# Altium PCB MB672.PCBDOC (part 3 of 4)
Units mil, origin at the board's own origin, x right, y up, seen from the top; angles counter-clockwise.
Board outline 4505 x 6805 mil, 4 copper layers (TopLayer, GND, VCC, BottomLayer); 337 components, 289 nets, 1516 pads, 621 vias.
Unrouted connection lines stored in the file: 46.
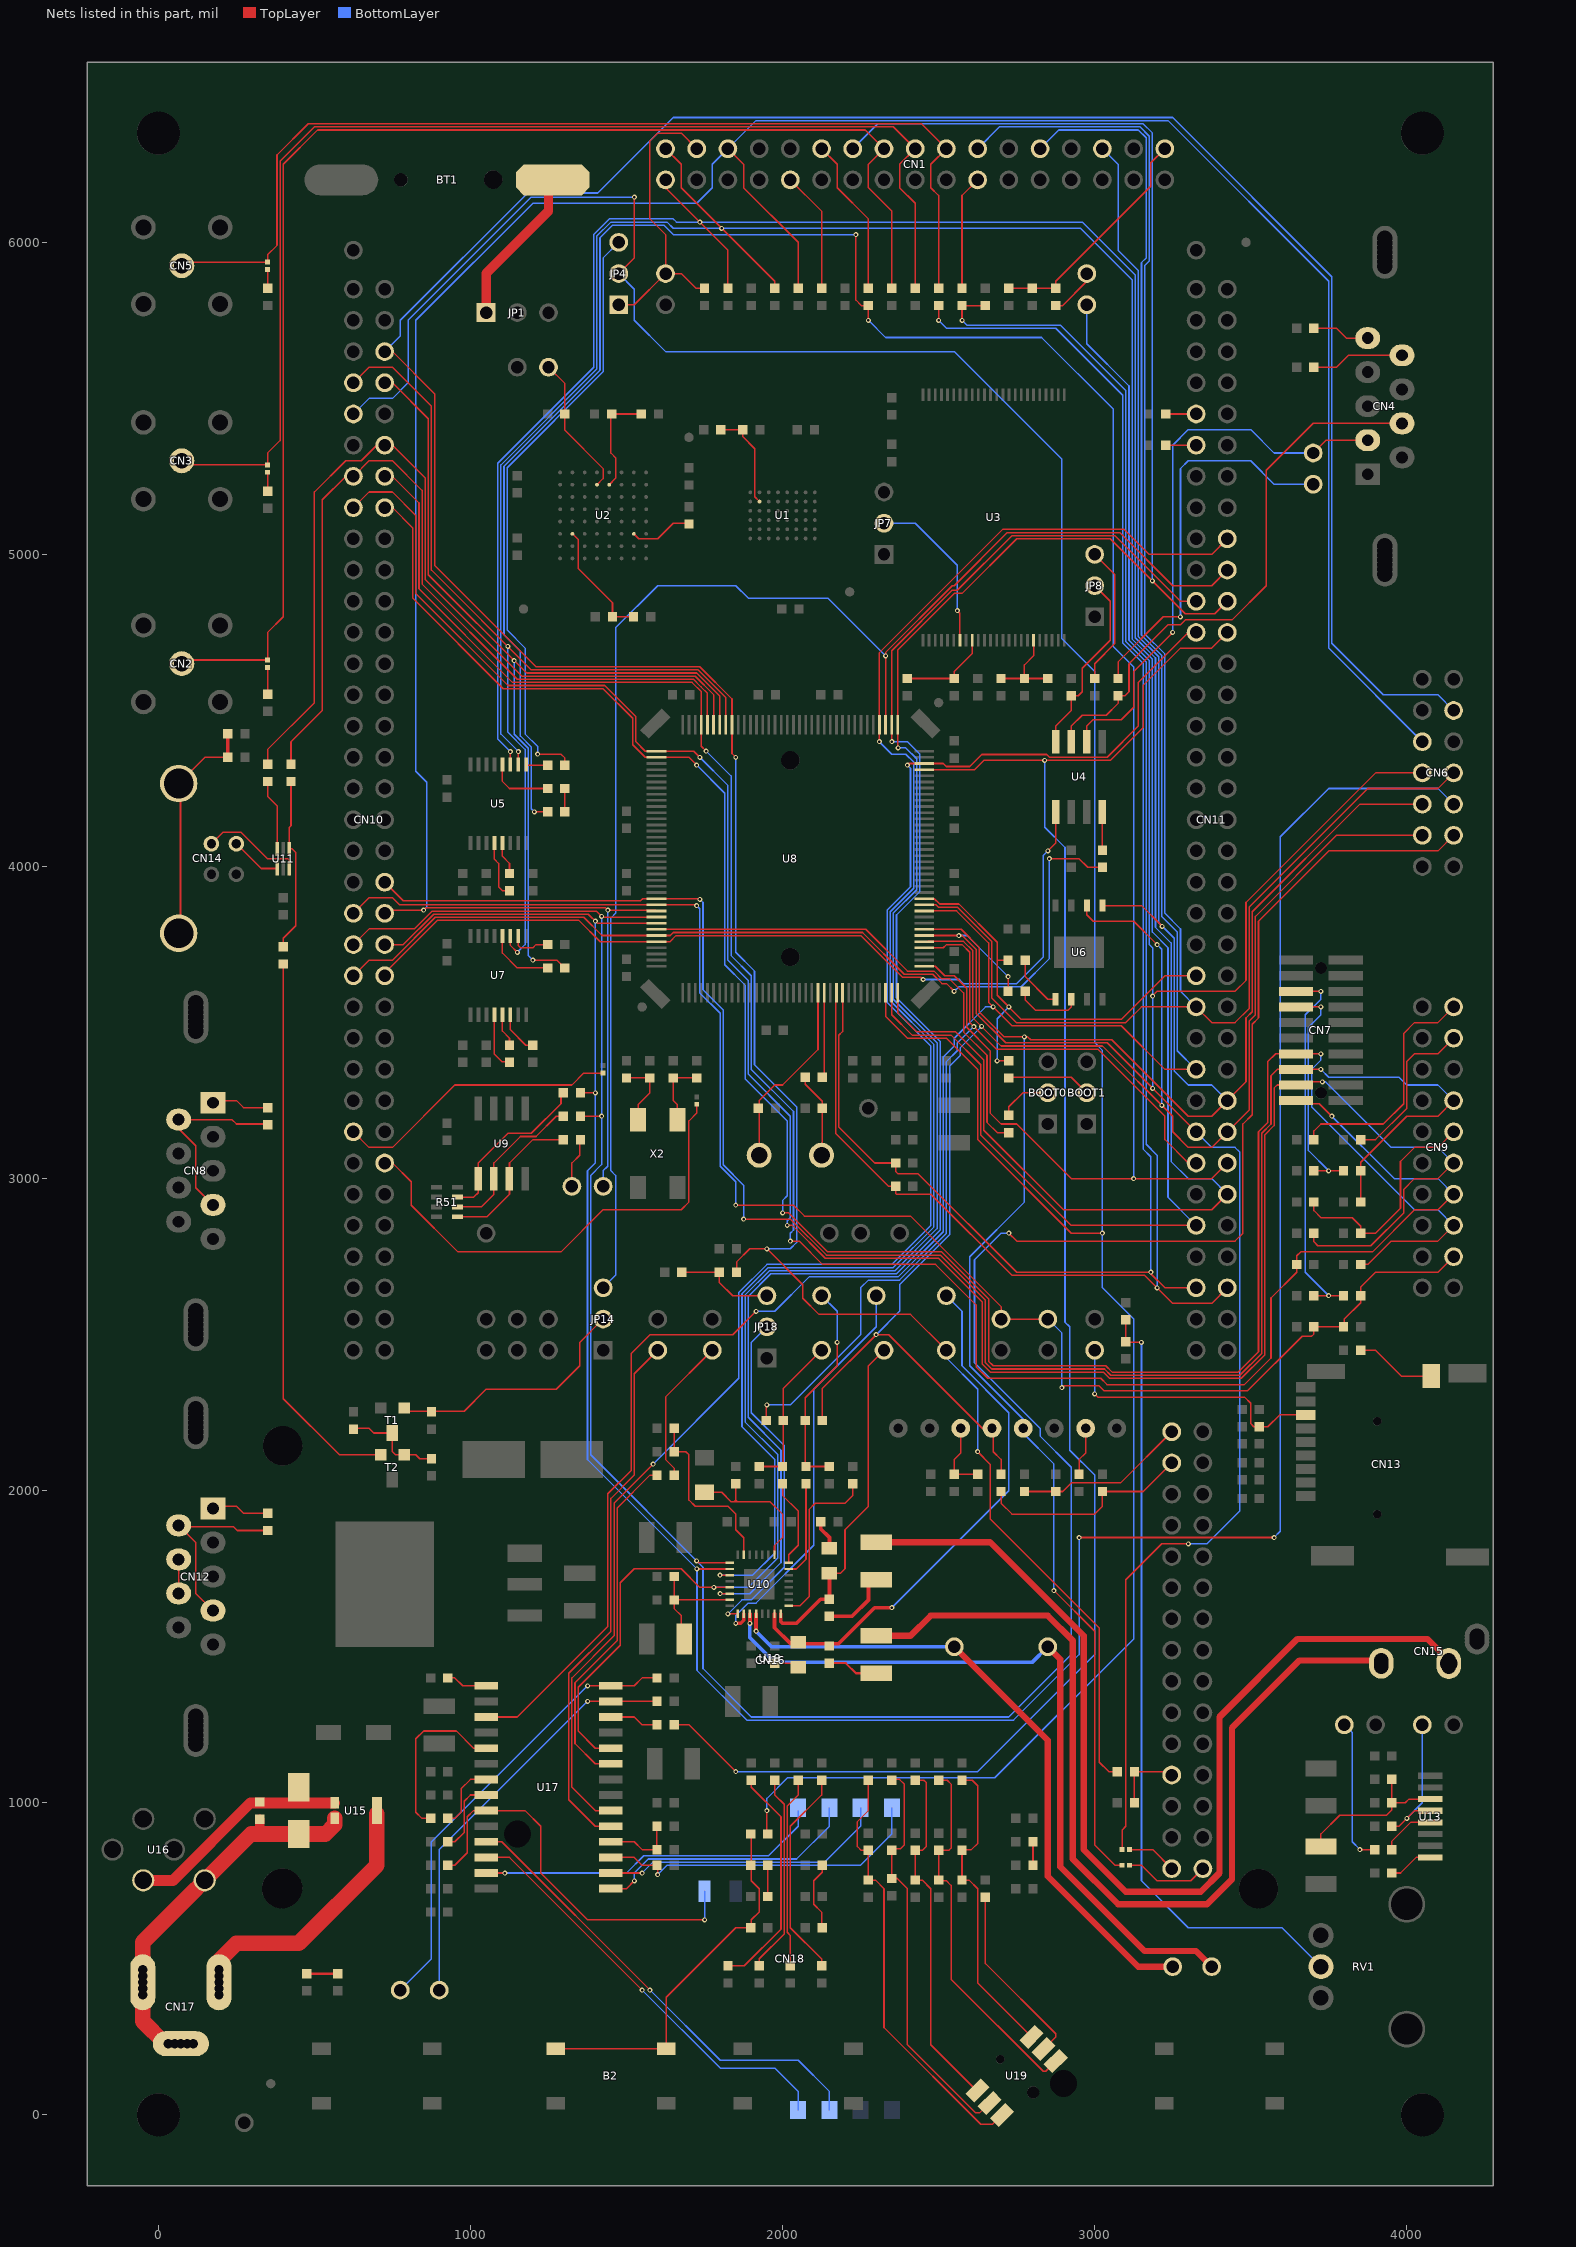
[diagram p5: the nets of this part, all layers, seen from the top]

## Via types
v1: diameter 16, hole 8, TopLayer to BottomLayer, tented both sides, 621 vias

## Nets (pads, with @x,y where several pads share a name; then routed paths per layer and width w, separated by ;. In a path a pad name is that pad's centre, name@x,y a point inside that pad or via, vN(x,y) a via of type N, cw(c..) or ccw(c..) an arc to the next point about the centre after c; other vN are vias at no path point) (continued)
NetC42_2: C42.2 U7.6 | length 140.5
  TopLayer w5: U7.6@1127.95,3525 1127.95,3477.05 1177.5,3427.5 C42.2@1200,3427.5
NetC43_1: C43.1 R135.1 X2.1 | length 225
  TopLayer w5: R135.1@1500,3322.5 C43.1@1575,3322.5 1575,3275 1537.01,3237.01 X2.1@1537.01,3188.27
NetC47_1: C47.1 U8.23 X1.2 | length 616.1
  TopLayer w5: X1.2@1902.5,3077.5 X1.2@1902.5,3080 ; X1.2@1925,3075 1925,3250 1975,3300 2000,3300 2113.58,3413.58 U8.23@2113.58,3595.87
NetC48_1: C48.1 R40.2 X1.1 | length 270.3
  TopLayer w5: R40.2@2072.5,3325 2072.5,3302.5 2127.5,3247.5 X1.1@2127.5,3077.5
NetC56_2: C55.2 C56.2 R67.1 TP9.1 | length 498.2
  TopLayer w5: C55.2@1925,2077.5 C56.2@2000,2077.5 C56.2@2000,2080 ; C56.2@2002.5,2080 2002.5,2327.5 TP9.1@2125,2450
NetC57_2: C57.2 C58.2 R68.1 TP6.1 | length 758.2
  TopLayer w5: C57.2@2072.5,2080 2072.5,2297.5 2175,2400 v1(2175,2475) ; C57.2@2075,2077.5 C58.2@2150,2077.5 C57.2@2075,2077.5
  BottomLayer w5: TP6.1@2125,2625 2175,2575 v1(2175,2475)
NetC59_1: C59.1 U10.25 | length 553.6
  TopLayer w5: U10.25@2019.49,1631.1 2056.1,1631.1 2085,1660 2085,1940 2105,1960 2200,1960 2225,1985 C59.1@2225,2022.5
NetC67_2: C67.2 R73.1 | length 96.4
  TopLayer w12: R73.1@2122.5,1900 2122.5,1877.5 2150,1850 C67.2@2150,1815
NetC70_2: C70.2 CN15.2 | length 3356.5
  TopLayer w20: C70.2@2300,1835 2665,1835 2965,1535 2965,850 3100,715 3340,715 3400,775 3400,1275 3650,1525 4065.71,1525 CN15.2@4134.45,1456.26
NetC76_2: C76.2 R86.1 | length 82.5
  TopLayer w5: R86.1@1975,1447.5 C76.2@2057.5,1447.5
NetC78_2: C78.2 CN14.0 R95.2 | length 759.9
  TopLayer w5: CN14.0@65,4266 149,4350 R95.2@222.5,4350 ; CN14.0@70.79,3779.21 CN14.0@70.79,4271.79
  TopLayer w12: R95.2@222.5,4350 C78.2@222.5,4425
NetC80_2: C80.2 CN15.3 | length 3045.7
  TopLayer w20: C80.2@2300,1535 2410,1535 2475,1600 2850,1600 2930,1520 2930,820 3075,675 3360,675 3440,755 3440,1240 3656.26,1456.26 CN15.3@3917.91,1456.26
NetC87_1: C87.1 U17.7 | length 218.2
  TopLayer w5: C87.1@927.5,950 950,950 970,970 970,1045 1000,1075 U17.7@1050,1075
NetC90_2: C90.2 CN18.1 U17.17 | length 1073.5
  TopLayer w5: U17.17@1450,825 1525,825 1550,800 C90.2@1597.5,800 ; v1(1600,770) C90.2@1600,797.5
  BottomLayer w5: v1(1600,770) 1630,800 2250,800 2350,900 CN18.1@2350,984.25
NetC91_1: C91.1 R120.2 | length 100
  TopLayer w5: R120.2@1952.5,700 C91.1@1952.5,800
NetC91_2: B2.2 B2.3 C91.2 R110.1 R123.1 | length 1197.3
  TopLayer w5: B2.2@1272.83,212.5 B2.3@1627.17,212.5 1627.17,377.17 1850,600 R123.1@1897.5,600 ; R123.1@1900,602.5 1900,625 1925,650 1925,725 1900,750 R110.1@1900,897.5
NetC92_1: C92.1 R124.2 | length 219.2
  TopLayer w5: R124.2@2125,602.5 2125,650 2100,675 2100,750 2127.5,777.5 C92.1@2127.5,800
NetC93_1: C93.1 R117.2 | length 75
  TopLayer w5: C93.1@2802.5,800 R117.2@2802.5,875
NetCN1_14: CN1.14 R6.1 | length 368.2
  TopLayer w5: R6.1@2575,5852.5 2575,6150 CN1.14@2625,6200
NetCN1_26: CN1.26 R1.1 | length 388.9
  TopLayer w5: CN1.26@2025,6200 2125,6100 R1.1@2125,5852.5
NetCN7_14: CN7.14 R49.1 R50.1 | length 743.5
  TopLayer w5: CN7.14@3645,3550 v1(3725,3550) ; R49.1@3702.5,3025 R50.1@3797.5,3025
  BottomLayer w5: v1(3725,3550) 3725,3525 3685,3485 3685,3090 v1(3750,3025)
NetCN7_16: CN7.16 R60.1 R61.1 | length 1201.8
  TopLayer w5: CN7.16@3645,3600 v1(3725,3600) ; R60.1@3702.5,2625 R61.1@3797.5,2625
  BottomLayer w5: v1(3725,3600) 3725,3575 3675,3525 3675,2700 v1(3750,2625)
NetCN9_11: CN9.11 R52.2 R55.1 | length 740.7
  TopLayer w5: R52.2@3702.5,2925 3702.5,2897.5 3725,2875 3825,2875 3852.5,2847.5 R55.1@3852.5,2825 3900,2825 3980,2905 3980,3055 4025,3100 4100,3100 CN9.11@4150,3150
NetCN9_17: CN9.17 R48.1 | length 520
  TopLayer w5: R48.1@3852.5,3125 3900,3125 4000,3225 4000,3375 4025,3400 4100,3400 CN9.17@4150,3450
NetCN9_19: CN9.19 R47.1 | length 771.5
  TopLayer w5: R47.1@3702.5,3125 3702.5,3152.5 3725,3175 3925,3175 3990,3240 3990,3465 4025,3500 4100,3500 CN9.19@4150,3550
NetCN10_58: CN10.58 JP10.1 | length 1526.8
  TopLayer w5: CN10.58@725,3050 750,3050 810,2990 810,2915 960,2765 1290,2765 1425,2900 1675,2900 1700,2925 1700,3185 1725,3210 JP10.1@1725,3238.19
NetCN12_7: CN12.7 CN12.8 | length 105
  TopLayer w5: CN12.8@65,1675 CN12.7@65,1780
NetCN14_2: CN14.2 U11.1 | length 163.2
  TopLayer w5: CN14.2@250,4073 329.3,3993.7 U11.1@380.32,3993.7
NetCN14_3: CN14.3 U11.3 | length 347.2
  TopLayer w5: CN14.3@170,4073 207,4110 265,4110 350,4025 415,4025 419.68,4020.32 U11.3@419.68,3993.7
  TopLayer w7: U11.3@419.68,3975.32 U11.3@419.68,3993.7
NetCN17_1: CN17.1 U15.1 | length 886.7
  TopLayer w50: CN17.1@194.09,405 194.09,494.09 250,550 450,550 700,800 U15.1@700,965
NetCN17_3: C85.2 CN17.2 CN17.3 U15.2 U16.2 Z1.1 | length 1270.5
  TopLayer w30: 325,900.2 C85.2@325,947.5
  TopLayer w50: CN17.2@100,230 20,230 -50,300 -50,553.15 297.05,900.2 535.2,900.2 565,930 U15.2@565,950
NetCN18_2: CN18.2 U17.16 | length 921.4
  TopLayer w5: U17.16@1450,775 v1(1550,775)
  BottomLayer w5: v1(1550,775) 1585,810 2135,810 2250,925 CN18.2@2250,984.25
NetCN18_3: CN18.3 U17.15 | length 856.7
  TopLayer w5: U17.15@1450,725 1500,725 v1(1525,750)
  BottomLayer w5: v1(1525,750) 1525,775 1570,820 2045,820 2150,925 CN18.3@2150,984.25
NetJP1_1: BT1.1 JP1.1 | length 915.7
  TopLayer w5: JP1.1@1050,5775 1050,5900 1250,6100
  TopLayer w30: JP1.1@1050,5775 1050,5900 1250,6100 BT1.1@1250,6200
NetJP3_2: JP3.2 R8.2 | length 157.1
  TopLayer w5: R8.2@2875,5797.5 2897.5,5797.5 2975,5875 JP3.2@2975,5900
NetJP4_1: C1.2 CN1.31 JP2.1 JP4.1 | length 962.9
  TopLayer w5: JP4.1@1475,5800 1525,5800 JP2.1@1625,5900 ; CN1.31@1725,6300 1675,6350 1600,6350 1575,6325 1575,6075 1625,6025 JP2.1@1625,5900 ; C1.2@1750,5852.5 1722.5,5852.5 1675,5900 JP2.1@1625,5900
NetJP4_3: JP4.3 R30.2 | length 1943.6
  TopLayer w5: v1(1215,4360) 1290,4360 1302.5,4347.5 R30.2@1302.5,4325
  BottomLayer w5: v1(1215,4360) 1215,4385 1175,4425 1175,4700 1117.5,4757.5 1117.5,5277.5 1425,5585 1425,5950 JP4.3@1475,6000
NetJP7_2: JP7.2 U3.7 | length 534.3
  TopLayer w5: v1(2560,4820) 2568.11,4811.89 U3.7@2568.11,4725
  BottomLayer w5: JP7.2@2325,5100 2425,5100 2560,4965 v1(2560,4820)
NetJP8_3: JP8.3 R27.1 | length 451.3
  TopLayer w5: R27.1@3000,4602.5 3000,4650 3065,4715 3065,4935 JP8.3@3000,5000
NetJP9_2: CN10.55 JP9.2 | length 919.4
  TopLayer w5: CN10.55@625,3150 675,3100 750,3100 950,3300 1325,3300 1363.19,3338.19 JP9.2@1425,3338.19
NetJP11_2: JP11.2 R46.2 | length 157.9
  TopLayer w5: JP11.2@1325,2975 1325,3050 1350,3075 R46.2@1350,3122.5
NetJP15_2: JP15.2 U17.19 | length 1728.3
  TopLayer w5: U17.19@1450,925 1400,925 1315,1010 1315,1415 1450,1550 1450,1975 1525,2050 1525,2375 JP15.2@1600,2450
NetJP16_2: JP16.2 R71.1 | length 473.5
  TopLayer w5: R71.1@1652.5,2050 1652.5,2072.5 1625,2100 1625,2300 JP16.2@1775,2450
NetJP17_2: CN13.7 JP17.2 R130.2 | length 913.9
  TopLayer w5: v1(3000,2310) 3010,2300 3480,2300 3500,2280 3500,2215 3510,2205 3555,2205 3592.91,2242.91 CN13.7@3676.65,2242.91
  BottomLayer w5: v1(3000,2310) JP17.2@3000,2450
NetJP18_2: JP18.2 U10.17 | length 1107.6
  TopLayer w5: v1(1825,1605) 1825.51,1605.51 U10.17@1856.1,1605.51
  BottomLayer w5: v1(1825,1605) 1870,1650 1900,1650 2005,1755 2005,2145 1900,2250 1900,2475 JP18.2@1950,2525
NetJP21_1: JP21.1 R88.1 U13.5 | length 463.8
  TopLayer w5: R88.1@3952.5,925 3975,925 4024.61,974.61 U13.5@4075,974.61
  BottomLayer w5: v1(4000,950) 4050,1000 JP21.1@4050,1250
NetJP22_2: JP22.2 R89.2 | length 468.2
  TopLayer w5: v1(3850,850) R89.2@3897.5,850
  BottomLayer w5: JP22.2@3800,1250 3825,1225 3825,875 v1(3850,850)
NetJP25_2: JP25.2 R138.1 | length 60.7
  TopLayer w5: R138.1@350,5852.5 JP25.2@350,5913.19
NetJP26_2: CN16.29 JP26.2 | length 160.5
  TopLayer w5: JP26.2@3111.81,850 3186,850 CN16.29@3247,789
NetJP27_2: CN16.30 JP27.2 | length 272.1
  TopLayer w5: JP27.2@3111.81,800 3150,800 3200,750 3308,750 CN16.30@3347,789
NetLD1_1: LD1.1 R96.1 | length 677.8
  TopLayer w5: LD1.1@2125,477.5 2125,500 2025,600 2025,925 2125,1025 R96.1@2125,1072.5
NetLD2_1: LD2.1 R97.1 | length 613.6
  TopLayer w5: LD2.1@2025,477.5 2025,575 2015,585 2015,990 2050,1025 R97.1@2050,1072.5
NetLD3_1: LD3.1 R98.1 | length 640.6
  TopLayer w5: LD3.1@1925,477.5 1925,500 2005,580 2005,995 1975,1025 R98.1@1975,1072.5
NetLD4_1: LD4.1 R99.1 | length 735.5
  TopLayer w5: LD4.1@1825,477.5 1877.5,477.5 1995,595 1995,955 1900,1050 R99.1@1900,1072.5
NetR2_2: CN1.23 R2.2 | length 509.6
  TopLayer w5: CN1.23@2125,6300 2175,6250 2175,6175 2275,6075 R2.2@2275,5852.5
NetR3_2: CN1.19 CN2.5 JP23.1 R3.2 | length 4376.8
  TopLayer w5: CN2.5@76.81,4661.81 JP23.1@350,4661.81 350,4750 400,4800 400,6250 510,6360 2265,6360 CN1.19@2325,6300 2275,6250 2275,6175 2350,6100 R3.2@2350,5852.5
NetR4_2: CN1.17 CN3.5 JP24.1 R4.2 | length 3850
  TopLayer w5: CN3.5@88.19,5286.81 JP24.1@350,5286.81 350,5325 390,5365 390,6260 500,6370 2355,6370 CN1.17@2425,6300 2375,6250 2375,6175 2425,6125 R4.2@2425,5852.5
NetR5_2: CN1.15 CN5.5 JP25.1 R5.2 | length 3316.9
  TopLayer w5: CN5.5@86.81,5936.81 JP25.1@350,5936.81 350,5960 380,5990 380,6280 480,6380 2445,6380 CN1.15@2525,6300 2475,6250 2475,6175 2500,6150 R5.2@2500,5852.5
NetR7_1: C8.2 CN1.1 R7.1 R8.1 | length 740
  TopLayer w5: C8.2@2725,5852.5 R8.1@2872.5,5852.5 ; R8.1@2875,5852.5 2875,5875 3180,6180 3180,6255 CN1.1@3225,6300
NetR9_2: CN4.5 R9.2 | length 185.8
  TopLayer w5: R9.2@3702.5,5725 3775,5725 3807,5693 CN4.5@3875,5693
NetR10_2: CN4.9 R10.2 | length 298.2
  TopLayer w5: R10.2@3702.5,5600 3775,5600 3813,5638 CN4.9@3985,5638
NetR11_2: CN11.9 R11.2 | length 97.5
  TopLayer w5: R11.2@3227.5,5450 CN11.9@3325,5450
NetR12_2: JP5.2 R12.2 U2.B4 | length 457.2
  TopLayer w5: JP5.2@1250,5600 1302.5,5547.5 1302.5,5397.5 1425,5275 1425,5243.11 U2.B4@1405.31,5223.43
NetR13_1: C10.1 R13.1 U2.B5 | length 333.7
  TopLayer w5: U2.B5@1444.68,5223.43 1465,5243.74 1465,5310 1450,5325 C10.1@1450,5447.5 ; C10.1@1452.5,5450 R13.1@1547.5,5450
NetR14_1: CN11.11 R14.1 | length 97.5
  TopLayer w5: R14.1@3227.5,5350 CN11.11@3325,5350
NetR16_2: R15.2 R16.2 U1.B5 | length 322.9
  TopLayer w5: R15.2@1802.5,5400 R16.2@1872.5,5400 1872.5,5377.5 1911,5339 1911,5184.47 U1.B5@1926.18,5169.29
NetR19_2: R19.2 U2.F7 | length 201.4
  TopLayer w5: U2.F7@1523.43,5065.94 1539.37,5050 1600,5050 1650,5100 R19.2@1697.5,5100
NetR20_1: R20.1 R21.2 U2.F2 | length 386.6
  TopLayer w5: U2.F2@1326.57,5065.94 1345,5047.52 1345,4955 1455,4845 R20.1@1455,4800 R21.2@1522.5,4800
NetR23_1: R22.2 R23.1 U3.9 | length 296.3
  TopLayer w5: R22.2@2400,4602.5 R23.1@2550,4602.5 2550,4625 2607.48,4682.48 U3.9@2607.48,4725
NetR26_1: JP8.2 R26.1 U4.8 | length 631.4
  TopLayer w5: U4.8@2875,4375 2875,4450 2925,4500 R26.1@2925,4547.5 2947.5,4547.5 2960,4560 2960,4635 3050,4725 3050,4850 JP8.2@3000,4900
NetR28_2: JP6.1 R28.2 | length 1254
  TopLayer w5: R28.2@3075,4602.5 3075,4655 3220,4800 v1(3275,4800)
  BottomLayer w5: v1(3275,4800) 3275,5275 3300,5300 3500,5300 3575,5225 JP6.1@3700,5225
NetR31_2: R29.2 R31.2 | length 75
  TopLayer w5: R31.2@1302.5,4175 R29.2@1302.5,4250
NetR32_1: R32.1 U4.4 | length 122.5
  TopLayer w5: R32.1@3025,4052.5 U4.4@3025,4175
NetR33_1: CN8.4 CN8.6 R33.1 | length 606.9
  TopLayer w5: CN8.4@175,2916 120,2971 120,3105 65,3160 CN8.6@65,3189 236,3189 250,3175 R33.1@347.5,3175
NetR33_2: CN8.1 R33.2 | length 189.3
  TopLayer w5: CN8.1@170,3250 250,3250 272.5,3227.5 R33.2@350,3227.5
NetR35_1: R35.1 U6.1 | length 180
  TopLayer w5: R35.1@2777.5,3700 2777.5,3647.5 2850,3575 U6.1@2875,3575
NetR37_2: R37.2 U6.2 | length 217.6
  TopLayer w5: R37.2@2777.5,3600 2777.5,3572.5 2810,3540 2915,3540 2925,3550 U6.2@2925,3575
NetR38_1: R38.1 R51.4 U9.1 | length 546.1
  TopLayer w5: R51.4@958.5,2940.75 1010.75,2940.75 1025,2955 1025,3050 1120,3145 1195,3145 1290,3240 R38.1@1290,3275
NetR40_1: R40.1 U8.24 | length 269.1
  TopLayer w5: R40.1@2133.27,3326.73 U8.24@2133.27,3595.87
NetR43_2: BOOT1.2 R43.2 | length 268.2
  TopLayer w5: R43.2@2727.5,3325 2925,3325 BOOT1.2@2975,3275
NetR44_1: R44.1 R51.6 U9.2 | length 518
  TopLayer w5: R51.6@958.5,2909.25 1034.25,2909.25 1075,2950 1075,3050 1160,3135 1210,3135 1275,3200 R44.1@1297.5,3200
NetR45_1: R45.1 U8.138 | length 1598
  TopLayer w5: U8.138@1595.87,3798.62 2266.38,3798.62 2400,3665 2485,3665 2510,3640 2535,3640 2580,3595 2580,3470 2655,3395 2655,3180 2687.5,3147.5 R45.1@2725,3147.5
NetR45_2: BOOT0.2 R45.2 | length 171.1
  TopLayer w5: R45.2@2725,3202.5 2725,3230 2770,3275 BOOT0.2@2850,3275
NetR46_1: R46.1 R51.8 U9.3 | length 500
  TopLayer w5: R51.8@958.5,2877.76 1052.76,2877.76 1125,2950 1125,3050 1200,3125 R46.1@1297.5,3125
NetR56_1: JP18.3 R56.1 R57.1 | length 322.6
  TopLayer w5: R56.1@1677.5,2700 R57.1@1797.5,2700 1797.5,2667.5 1840,2625 JP18.3@1950,2625
NetR62_1: CN12.4 CN12.6 R62.1 | length 604.7
  TopLayer w5: CN12.6@65,1889 120,1834 120,1671 CN12.4@175,1616 ; CN12.6@69,1885 240,1885 252.5,1872.5 R62.1@350,1872.5
NetR62_2: CN12.1 R62.2 | length 177.3
  TopLayer w5: CN12.1@182,1950 250,1950 272.5,1927.5 R62.2@350,1927.5
NetR69_1: R69.1 T2.1 | length 1779.6
  TopLayer w5: R69.1@400,3687.5 400,2295 580,2115 T2.1@712.5,2115
NetR70_2: R65.1 R70.2 T1.3 T2.2 | length 322.7
  TopLayer w5: R65.1@627.5,2200 675,2200 690,2185 T1.3@749.5,2185 749.5,2125.5 760,2115 825,2115 837.5,2102.5 R70.2@875,2102.5
NetR74_2: R74.2 R76.1 U18.3 | length 231.2
  TopLayer w5: U18.3@2571.06,2200 2571.06,2121.06 2550,2100 R74.2@2550,2052.5 R76.1@2625,2052.5
NetR75_1: CN16.3 R75.1 R80.2 | length 694.8
  TopLayer w5: R75.1@2700,1997.5 2700,1960 2735,1925 3000,1925 3025,1950 R80.2@3025,1997.5 3155.5,1997.5 CN16.3@3247,2089
NetR78_2: CN16.1 R77.2 R78.2 | length 551.3
  TopLayer w5: R77.2@2775,1997.5 2897.5,1997.5 2925,2025 3083,2025 CN16.1@3247,2189
NetR79_2: R79.2 U18.7 | length 163.7
  TopLayer w5: R79.2@2950,2045 2950,2100 2971.06,2121.06 U18.7@2971.06,2200
NetR83_1: C66.1 C73.1 R83.1 U10.15 | length 386.5
  TopLayer w5: C66.1@1652.5,1725 1652.5,1622.5 1675,1600 C73.1@1675,1525 ; R83.1@1653.29,1650.79 U10.15@1830.51,1650.79
NetR84_1: C70.1 R84.1 | length 211.7
  TopLayer w12: R84.1@2150,1597.5 2222.5,1597.5 2275,1650 C70.1@2275,1715
NetR85_2: C72.1 C77.1 R85.2 U13.6 | length 524.6
  TopLayer w5: C77.1@3725,860 3725,900 3785,960 3935,960 3952.5,977.5 C72.1@3952.5,1075 ; R85.2@3952.5,1000 3995,1000 4007.01,1012.01 U13.6@4075,1012.01
NetR87_1: C80.1 R87.1 | length 163.5
  TopLayer w7: R87.1@2150,1447.5 2202.5,1447.5 2235,1415 C80.1@2300,1415
NetR89_1: R89.1 U13.4 | length 174.7
  TopLayer w5: R89.1@3952.5,850 3952.5,877.5 4012.2,937.2 U13.4@4075,937.2
NetR90_2: R90.2 U17.1 | length 132.9
  TopLayer w5: R90.2@927.5,1400 950,1400 975,1375 U17.1@1050,1375
NetR92_2: R92.2 U13.1 | length 143.2
  TopLayer w5: R92.2@3952.5,775 3980,775 4030,825 U13.1@4075,825
NetR100_1: C95.2 R100.1 R112.1 U19.3 | length 1389.5
  TopLayer w5: R112.1@2275,847.5 2252.5,847.5 2240,860 2240,940 2275,975 R100.1@2275,1072.5 ; R112.1@2275,850 C95.2@2275,752.5 2297.5,752.5 2325,725 2325,280 2635,-30 2672.95,-30 U19.3@2702.67,-0.27
NetR101_1: C96.2 R101.1 R113.2 U19.2 | length 1309.1
  TopLayer w5: R101.1@2352.5,1075 2375,1075 2390,1060 2390,865 2377.5,852.5 2350,852.5 C96.2@2350,757.5 2367.5,757.5 2400,725 2400,225 2617.6,7.4 2632.4,7.4 U19.2@2663.7,38.7
NetR102_1: C97.2 R102.1 R114.1 U19.1 | length 1150.4
  TopLayer w5: R102.1@2425,1072.5 2452.5,1072.5 2460,1065 2460,860 2447.5,847.5 R114.1@2425,847.5 C97.2@2425,752.5 2447.5,752.5 2475,725 2475,225 2622.33,77.67 U19.1@2624.73,77.67
NetR103_1: C98.2 R103.1 R115.1 U19.4 | length 1206.4
  TopLayer w5: R103.1@2500,1072.5 2527.5,1072.5 2540,1060 2540,855 2532.5,847.5 R115.1@2500,847.5 C98.2@2500,752.5 2502.5,750 2525,750 2540,735 2540,435 2835,140 2842.95,140 U19.4@2875.27,172.33
NetR104_1: C99.2 R104.1 R116.1 U19.6 | length 1000.5
  TopLayer w5: R116.1@2575,847.5 C99.2@2575,752.5 2597.5,752.5 2625,725 2625,422.6 U19.6@2797.33,250.27 ; R104.1@2575,1072.5 2607.5,1072.5 2625,1055 2625,870 2605,850 R116.1@2577.5,850
NetR105_1: CN16.23 R105.1 R107.1 | length 224.1
  TopLayer w5: R107.1@3127.5,1000 R105.1@3127.5,1100 3236,1100 CN16.23@3247,1089
NetR125_2: R125.2 U19.5 | length 595.4
  TopLayer w5: R125.2@2650,697.5 2650,485 2875,260 2875,250 U19.5@2836.3,211.3
NetR126_2: C100.2 R126.2 RV1.2 | length 2534.9
  TopLayer w5: R126.2@3100,2547.5 C100.2@3100,2477.5 3102.5,2475 v1(3150,2475)
  BottomLayer w5: v1(3150,2475) 3150,750 3300,600 3600,600 RV1.2@3725,475
NetR127_1: LD5.1 R127.1 | length 100
  TopLayer w7: LD5.1@475,452.5 R127.1@575,452.5
NetR128_1: R72.1 R128.1 U10.7 | length 581.5
  TopLayer w5: R128.1@1652.5,2200 R72.1@1652.5,2125 1690,2125 1700,2115 1700,1970 1720,1950 1825,1950 1850,1925 1850,1875 1875.79,1849.21 U10.7@1875.79,1794.49
NetR129_2: CN13.10 R129.2 | length 260.1
  TopLayer w5: R129.2@3852.5,2450 3900,2450 3983.07,2366.93 CN13.10@4078.23,2366.93
NetR136_1: JP23.2 R136.1 | length 85.7
  TopLayer w5: R136.1@350,4552.5 JP23.2@350,4638.19
NetR137_1: JP24.2 R137.1 | length 60.7
  TopLayer w5: R137.1@350,5202.5 JP24.2@350,5263.19
NetT1_2: JP14.2 R66.1 T1.2 | length 806.1
  TopLayer w5: T1.2@785,2255 980,2255 1050,2325 1275,2325 1350,2400 1350,2475 JP14.2@1425,2550
NetTP7_1: TP7.1 U10.18 | length 1301.5
  TopLayer w12: v1(1850,1575) 1865.79,1575 1875.79,1585 U10.18@1875.79,1605.51
  BottomLayer w5: v1(1850,1575) 1850,1600 1890,1640 1915,1640 2100,1825 2100,2325 2300,2525 TP7.1@2300,2625
NetU3_19: C21.2 R24.2 R25.1 U3.19 | length 284.6
  TopLayer w5: R24.2@2700,4602.5 C21.2@2850,4602.5 ; R25.1@2775,4602.5 2775,4645.67 2804.33,4675 U3.19@2804.33,4725
NetU4_6: CN4.2 JP6.2 U4.6 | length 1820.4
  TopLayer w5: U4.6@2975,4390 2975,4450 2995,4470 3085,4470 3125,4510 3125,4625 v1(3250,4750) ; JP6.2@3700,5325 3741,5366 CN4.2@3875,5366
  BottomLayer w5: v1(3250,4750) 3250,5350 3300,5400 3500,5400 3575,5325 JP6.2@3700,5325
NetU4_7: CN4.7 R28.1 U4.7 | length 1805.9
  TopLayer w5: U4.7@2925,4390 2925,4450 2960,4485 3037.5,4485 3075,4522.5 R28.1@3075,4547.5 3097.5,4547.5 3110,4560 3110,4650 3235,4775 3275,4775 3290,4790 3440,4790 3550,4900 3550,5270 3700,5420 CN4.7@3985,5420
NetU5_4: C30.1 U5.4 | length 185.7
  TopLayer w5: U5.4@1076.77,4075 1076.77,4023.23 1090,4010 1090,3935 1102.5,3922.5 C30.1@1125,3922.5
NetU5_5: C30.2 U5.5 | length 106.9
  TopLayer w5: U5.5@1102.36,4075 1102.36,4032.64 1125,4010 C30.2@1125,3977.5
NetU5_9: R30.1 U5.9 | length 66.4
  TopLayer w5: U5.9@1181.1,4325 R30.1@1247.5,4325
NetU5_12: R29.1 U5.12 | length 208.8
  TopLayer w5: U5.12@1102.36,4326.97 1102.36,4272.64 1125,4250 R29.1@1247.5,4250
NetU7_4: C40.1 U7.4 | length 182.1
  TopLayer w5: U7.4@1076.77,3525 1076.77,3398.23 1100,3375 C40.1@1122.5,3375
NetU7_5: C40.2 U7.5 | length 106.9
  TopLayer w5: U7.5@1102.36,3525 1102.36,3472.64 1125,3450 C40.2@1125,3427.5
NetU7_10: R34.1 U7.10 | length 131.3
  TopLayer w5: U7.10@1153.54,3776.97 1153.54,3746.46 1160,3740 1200,3740 1210,3750 R34.1@1247.5,3750
NetU7_12: R36.1 U7.12 | length 219.2
  TopLayer w5: U7.12@1102.36,3776.97 1102.36,3722.64 1150,3675 R36.1@1247.5,3675
NetU10_2: C53.1 C54.1 U10.2 | length 491.8
  TopLayer w5: C53.1@1750,1995 1805,1995 1835,1965 1960,1965 2000,1925 2000,1850 1974.21,1824.21 U10.2@1974.21,1794.49 ; 1845,1965 1850,1970 1855,1965 ; 1850,1965 C54.1@1850,2022.5
NetU10_19: TP13.1 U10.19 U14.2 | length 2424.1
  TopLayer w7: U10.19@1895,1605.04 U10.19@1895.47,1605.51
  TopLayer w12: v1(1895,1575) 1895.47,1575.47 U10.19@1895.47,1605.51
  TopLayer w20: U14.2@2849.61,1500 2890,1459.61 2890,795 3160,525 3325,525 TP13.1@3375,475
  BottomLayer w12: v1(1895,1575) 1895,1530 1975,1450 2799.61,1450 U14.2@2849.61,1500
NetU10_20: TP12.1 U10.20 U14.1 | length 2091.1
  TopLayer w5: U10.20@1915,1605.35 U10.20@1915.16,1605.51
  TopLayer w7: v1(1915,1550) v1@1915.16,1550.16
  TopLayer w12: v1@1915.16,1550.16 U10.20@1915.16,1605.51
  TopLayer w20: U14.1@2550.39,1500 2850,1200.39 2850,765 3140,475 TP12.1@3250,475
  BottomLayer w12: v1(1915,1550) 1965,1500 U14.1@2550.39,1500
NetU10_23: C76.1 R87.2 TP8.1 U10.23 | length 1727.4
  TopLayer w12: U10.23@1974.21,1605.51 1974.21,1560.79 2025,1510 2180,1510 2295,1625 v1(2350,1625)
  BottomLayer w5: v1(2350,1625) 2725,2000 2725,2250 2575,2400 2575,2575 TP8.1@2525,2625
NetU10_24: C67.1 R84.2 TP10.1 U10.24 | length 1105.6
  TopLayer w5: C67.1@2150,1735 2185,1735 2200,1750 2200,1875 2275,1950 2275,2400 TP10.1@2325,2450
  TopLayer w12: U10.24@1993.9,1605.51 1993.9,1581.1 2000,1575 2044.49,1575 2121.99,1652.5 R84.2@2150,1652.5 C67.1@2150,1735
NetU10_31: C57.1 U10.31 | length 310.8
  TopLayer w5: U10.31@2019.49,1749.21 2044.21,1749.21 2075,1780 C57.1@2075,2022.5
NetU10_32: C56.1 U10.32 | length 287
  TopLayer w5: C56.1@2000,2022.5 2000,1985 2050,1935 2050,1825 2019.49,1794.49 U10.32@2019.49,1768.9
NetU11_4: R69.2 R82.2 U11.4 | length 562.5
  TopLayer w5: R69.2@400,3742.5 400,3770 440,3810 440,4045 428.7,4056.3 U11.4@419.68,4056.3 419.68,4125 425,4130.32 R82.2@425,4272.5
NetU11_6: R81.2 U11.6 | length 228.8
  TopLayer w5: R81.2@350,4272.5 350,4225 380.32,4194.68 U11.6@380.32,4056.3
NetU15_3: C85.1 U15.3 U16.1 Z1.2 | length 716.3
  TopLayer w35: U16.1@-48.43,751.57 46.57,751.57 295,1000 U15.3@565,1000
NetU17_5: C87.2 U17.5 | length 548.9
  TopLayer w5: C87.2@872.5,950 845,950 825,970 825,1205 850,1230 955,1230 1010,1175 U17.5@1050,1175
NetU17_8: C89.1 U17.8 | length 243.2
  TopLayer w5: C89.1@927.5,875 950,875 980,905 980,1005 1000,1025 U17.8@1050,1025
NetU17_9: CN18.18 R118.2 U17.9 | length 1286.7
  TopLayer w5: R118.2@927.5,800 950,800 990,840 990,955 1010,975 1175,975 1225,925 1225,775 1375,625 v1(1750,625)
  BottomLayer w5: v1(1750,625) CN18.18@1750,716.54
NetU17_11: CN18.7 U17.11 | length 1490.6
  TopLayer w5: U17.11@1050,875 1100,875 v1(1575,400)
  BottomLayer w5: v1(1575,400) 1800,175 2050,175 2150,75 CN18.7@2150,15.75
NetU17_12: CN18.8 U17.12 | length 1369.9
  TopLayer w5: U17.12@1050,825 1125,825 v1(1550,400)
  BottomLayer w5: v1(1550,400) 1800,150 1975,150 2050,75 CN18.8@2050,15.75
NetU17_13: CN18.4 U17.13 | length 1112.1
  TopLayer w5: U17.13@1050,775 v1(1110,775)
  BottomLayer w5: v1(1110,775) 1500,775 1555,830 1955,830 2050,925 CN18.4@2050,975
NetU17_18: R108.1 R109.2 U17.18 | length 232.9
  TopLayer w5: U17.18@1450,875 1525,875 1550,850 R108.1@1597.5,850 R109.2@1597.5,925
NetU17_23: R71.2 U17.23 | length 1123.8
  TopLayer w5: U17.23@1450,1125 1400,1125 1335,1190 1335,1385 1470,1520 1470,1945 1575,2050 R71.2@1597.5,2050
NetU17_26: R94.1 U17.26 | length 157.9
  TopLayer w5: U17.26@1450,1275 1525,1275 1550,1250 R94.1@1597.5,1250
NetU17_27: R93.2 TP15.1 U17.27 | length 1351.8
  TopLayer w5: v1(1375,1325) R93.2@1605,1325
  BottomLayer w5: TP15.1@900,400 900,850 v1(1375,1325)
NetU17_28: R91.2 TP14.1 U17.28 | length 1456.4
  TopLayer w5: v1(1375,1375) 1525,1375 1550,1400 R91.2@1597.5,1400
  BottomLayer w5: TP14.1@775,400 875,500 875,875 v1(1375,1375)
NetX2_4: C44.1 R39.1 X2.4 | length 214.6
  TopLayer w5: X2.4@1662.99,3188.27 1662.99,3237.01 1650,3250 C44.1@1650,3322.5 R39.1@1725,3322.5
PA0: CN10.9 JP4.2 R110.2 U8.34 | length 9862.3
  TopLayer w5: JP4.2@1475,5900 1525,5950 v1(1525,6145) ; R110.2@1950,902.5 v1(1950,975) ; R110.2@1952.5,900 R110.2@1952.5,902.5 ; U8.34@2330.12,3595.87 2330.12,3519.88 2400,3450 2525,3450 2625,3350 2625,3125 2925,2825 v1(3025,2825)
  BottomLayer w5: CN10.9@625,5450 675,5500 750,5500 800,5550 800,5750.34 1194.66,6145 v1(1525,6145) ; JP4.2@1475,5900 1525,5850 1525,5750 1625,5650 2550,5650 2895,5305 2895,4730 3000,4625 3000,3435.86 3025,3410.86 3025,2650 3125,2550 3125,1525 2680,1080 2016.11,1080 1950,1013.89 v1(1950,975)
PA1: C4.2 CN1.33 CN11.61 U5.10 U8.35 | length 8818.6
  TopLayer w5: U5.10@1153.54,4326.97 v1(1153.54,4368.54) ; CN1.33@1625,6300 1675,6250 1675,6175 1975,5875 C4.2@1975,5852.5 ; U8.35@2349.8,3595.87 2349.8,3525.2 2415,3460 2540,3460 2635,3365 2635,3140 2925,2850 CN11.61@3325,2850
  BottomLayer w5: v1(1153.54,4368.54) 1097.5,4424.59 1097.5,5286.64 1405,5594.14 1405,6020 1450,6065 1630,6065 1650,6045 2955,6045 3120,5880 3120,4729 3185,4664 3185,3790 3235,3740 3235,2940 CN11.61@3325,2850
  other v1: 1805,6045
PA2: C3.2 CN1.34 CN11.60 U5.11 U8.36 | length 8748.5
  TopLayer w5: U5.11@1127.95,4326.97 v1(1127.95,4367.95) ; CN1.34@1625,6200 1625,6175 1825,5975 C3.2@1825,5852.5 ; U8.36@2369.49,3595.87 2369.49,3530.51 2430,3470 2555,3470 2645,3380 2645,3155 2900,2900 3375,2900 CN11.60@3425,2950
  BottomLayer w5: v1(1127.95,4367.95) 1087.5,4408.41 1087.5,5292.5 1395,5600 1395,6025 1445,6075 1650,6075 1660,6065 v1(1734.97,6065.03) ; v1(1734.97,6065.03) 2960,6065 3130,5895 3130,4733.14 3195,4668.14 3195,3805 3245,3755 3245,3055 3300,3000 3375,3000 CN11.60@3425,2950
PA3: CN11.58 R2.1 R31.1 U8.37 | length 8062.8
  TopLayer w5: v1(1205,4175) R31.1@1247.5,4175 ; v1(2235,6025) 2235,5815 2252.5,5797.5 R2.1@2275,5797.5 v1(2275,5750) ; U8.37@2454.13,3680.51 2489.49,3680.51 2520,3650 2550,3650 2590,3610 2590,3485 2665,3410 2665,3210 2700,3175 2750,3175 2925,3000 3375,3000 CN11.58@3425,3050
  BottomLayer w5: v1(1205,4175) 1195,4185 1195,4383.28 1160,4418.28 1160,4690 1107.5,4742.5 1107.5,5282.5 1415,5590 1415,6015 1455,6055 1620,6055 1650,6025 v1(2235,6025) ; v1(2275,5750) 2330,5695 2830,5695 3060,5465 3060,4704.14 3125,4639.14 v1(3125,3000)
PA4: CN11.57 R67.2 U8.40 | length 2981.2
  TopLayer w5: R67.2@1947.5,2225 1947.5,2272.5 v1(1950,2275) ; U8.40@2454.13,3739.57 2514.57,3739.57 2525,3750 2575,3750 2600,3725 2600,3500 2685,3415 3010,3415 3225,3200 3225,3125 3300,3050 CN11.57@3325,3050
  BottomLayer w5: v1(1950,2275) 2025,2275 2250,2500 2250,2650 2275,2675 2375,2675 2525,2825 2525,3375 2560,3410 2560,3434.57 v1(2612.71,3487.29)
PA5: CN6.4 CN11.56 R68.2 R75.2 U6.6 U8.41 U18.4 | length 5716.8
  TopLayer w5: R68.2@2127.5,2225 2127.5,2327.5 v1(2300,2500) 2340,2500 2640,2200 U18.4@2671.06,2200 ; U8.41@2465.75,3760 2580,3760 2610,3730 2610,3515 2700,3425 3025,3425 3250,3200 3250,3150 3300,3100 3375,3100 3495,3220 3495,3505 3515,3525 3515,3840 3775,4100 CN6.4@4050,4100 ; U18.4@2675,2196.06 2675,2125 2700,2100 R75.2@2700,2052.5 ; U6.6@2975,3875 2975,3845.47 2995.47,3825 3125,3825 v1(3200,3750)
  BottomLayer w5: v1(2300,2500) 2375,2575 2375,2660 2535,2820 2535,3360 2570,3395 2570,3419.89 v1(2637.55,3487.45) ; v1(3200,3750) 3215,3735 v1(3215,3235)
PA6: CN6.8 CN11.55 JP3.1 JP26.1 R37.1 U8.42 | length 8058.6
  TopLayer w5: U8.42@2454.13,3778.94 2576.06,3778.94 2620,3735 2620,3530 2715,3435 3040,3435 CN11.55@3325,3150 ; R37.1@2722.5,3600 v1(2722.5,3647.5) ; JP26.1@3088.19,850 3088.19,913.19 3100,925 3100,1715 3215,1830 v1(3300,1830) ; v1@3185.48,3585.48 3200,3600 3450,3600 3485,3635 3485,3885 3900,4300 CN6.8@4050,4300
  BottomLayer w5: v1(2565,3778.94) 2591.06,3778.94 v1(2722.5,3647.5) ; JP3.1@2975,5800 2975,5675 3110,5540 3110,4724.85 3175,4659.85 3175,3750 3185.48,3739.52 v1(3185.48,3289.52) ; v1(3300,1830) 3360.29,1830 3465,1934.71 3465,3085 3450,3100 3375,3100 CN11.55@3325,3150
  other v1: 3185.48,3585
PA7: CN1.5 CN6.6 CN11.54 JP27.1 U6.5 U8.43 U18.5 | length 9107.7
  TopLayer w5: U8.43@2454.13,3798.62 2572.24,3798.62 2630,3740.86 2630,3534.14 2710.14,3454 2786,3454 2795,3445 3055,3445 3300,3200 3375,3200 3485,3310 3485,3515 3505,3535 3505,3855 3850,4200 CN6.6@4050,4200 ; v1(2869.5,1680) 3000,1549.5 3000,865 3065,800 JP27.1@3088.19,800 ; U6.5@3025,3875 3150,3875 v1(3216.52,3808.48)
  BottomLayer w5: v1(2775,3454) 2775,2925 2600,2750 2600,2400 2771.06,2228.94 2771.06,2183.94 2869.5,2085.5 v1(2869.5,1680) ; CN1.5@3025,6300 3075,6250 3075,5975 3140,5910 3140,4737.28 3205,4672.28 3205,3820 3255,3770 3255,3345 3300,3300 3375,3300 CN11.54@3425,3250
PA8: CN6.11 CN10.6 R57.2 R105.2 TP11.1 U8.100 | length 11543
  TopLayer w5: CN10.6@725,5650 750,5650 885,5515 885,4965 1210,4640 1735,4640 1837.99,4537.01 1837.99,4362.01 v1(1850,4350) ; R57.2@1852.5,2700 1852.5,2732.5 1895,2775 v1(1950,2775) 2065,2660 2065,2616.57 2116.57,2565 2410,2565 TP11.1@2525,2450 ; v1(2625,2125) 2665,2085 2665,1910 3015,1560 3015,1130 3045,1100 R105.2@3072.5,1100
  BottomLayer w5: CN10.6@725,5650 775,5700 775,5750 1183.17,6158.17 1408.17,6158.17 1650,6400 3250,6400 3760,5890 3760,4715 3925,4550 4100,4550 CN6.11@4150,4500 ; v1(1850,4350) 1850,3725 1910,3665 1910,3365 2045,3230 2045,2795 2025,2775 v1(1950,2775) ; TP11.1@2525,2450 2525,2425 2625,2325 v1(2625,2125)
PA9: CN10.7 U7.11 U8.101 | length 3121.7
  TopLayer w5: CN10.7@625,5550 675,5600 750,5600 875,5475 875,4950 1195,4630 1730,4630 1818.31,4541.69 U8.101@1818.31,4454.13 ; U7.11@1127.95,3776.97 1127.95,3747.05 v1(1150,3725)
  BottomLayer w5: v1(1120,4705) 1120,4430 1175,4375 1175,3750 v1(1150,3725)
PA10: CN10.8 R36.2 U8.102 | length 2972.2
  TopLayer w5: CN10.8@725,5550 750,5550 865,5435 865,4935 1180,4620 1725,4620 1798.62,4546.38 U8.102@1798.62,4454.13 ; v1(1200,3700) 1277.5,3700 R36.2@1302.5,3675
  BottomLayer w5: v1(1140,4660) 1140,4424.14 1185,4379.14 1185,3715 v1(1200,3700)
PA11: CN10.12 R81.1 U8.103 | length 2893.9
  TopLayer w5: R81.1@350,4327.5 350,4375 500,4525 500,5200 600,5300 650,5300 700,5350 750,5350 855,5245 855,4920 1165,4610 1720,4610 1778.94,4551.06 U8.103@1778.94,4454.13
PA12: CN10.13 R82.1 U8.104 | length 2760.1
  TopLayer w5: R82.1@425,4327.5 425,4400 525,4500 525,5175 600,5250 CN10.13@625,5250 675,5300 750,5300 845,5205 845,4905 1150,4600 1714.25,4600 1738.9,4575.36 1759.25,4555 U8.104@1759.25,4454.13
PA13: CN7.2 CN9.7 CN10.14 R58.1 U8.105 | length 6850.8
  TopLayer w5: CN10.14@725,5250 750,5250 835,5165 835,4890 1135,4590 1710,4590 1739.57,4560.43 1739.57,4385.43 v1(1755,4370) ; v1(2025,2800) 2053.28,2800 2128.28,2725 2490,2725 2620,2595 2620,2397.43 2657.43,2360 3019.14,2360 3039.14,2340 3480,2340 3565,2425 3565,2617.5 3647.5,2700 3647.5,2752.5 3660,2765 3890,2765 4025,2900 4100,2900 CN9.7@4150,2950 ; CN7.2@3595,3240 3720,3240 v1(3760,3200)
  BottomLayer w5: v1(1755,4370) 1835,4290 1835,3715 1900,3650 1900,3350 2035,3215 2035,2835 2025,2825 v1(2025,2800) ; v1(3760,3200) 3960,3000 4100,3000 CN9.7@4150,2950
PA14: CN7.4 CN9.9 CN10.15 R54.2 U8.109 | length 7369.6
  TopLayer w5: CN10.15@625,5150 675,5200 750,5200 825,5125 825,4875 1120,4580 1430,4580 1530,4480 1530,4399.49 1560,4369.49 1715.51,4369.49 v1(1735,4350) ; v1(2015,2850) 2031.57,2850 2136.57,2745 2500,2745 2640,2605 2640,2405.71 2665.71,2380 3027.43,2380 3047.43,2360 3470,2360 3545,2435 3545,3140 3575,3170 3575,3290 3585,3300 CN7.4@3645,3300 ; CN7.4@3645,3310 v1(3730,3310) ; R54.2@3702.5,2825 3702.5,2797.5 3715,2785 3885,2785 3990,2890 3990,2965 4025,3000 4100,3000 CN9.9@4150,3050
  BottomLayer w5: v1(1735,4350) 1825,4260 1825,3700 1890,3635 1890,3335 2025,3200 2025,2875 2015,2865 v1(2015,2850) ; v1(3730,3310) 3740,3310 3950,3100 4100,3100 CN9.9@4150,3050
PA15: CN7.8 CN9.5 CN10.16 R59.1 U8.110 | length 7232
  TopLayer w5: CN10.16@725,5150 750,5150 815,5085 815,4860 1105,4570 1425,4570 1520,4475 1520,4389.8 1560,4349.8 1700.2,4349.8 v1(1725,4325) ; v1(2000,2890) 2019.85,2890 2144.85,2765 2510,2765 2660,2615 2660,2415 2675,2400 3035.71,2400 3055.71,2380 3460,2380 3525,2445 3525,3150 3555,3180 3555,3375 3580,3400 v1(3725,3400) ; R59.1@3852.5,2725 3875,2725 3950,2800 4100,2800 CN9.5@4150,2850
  BottomLayer w5: v1(1725,4325) 1815,4235 1815,3685 1880,3620 1880,3320 2015,3185 2015,2945 2000,2930 v1(2000,2890) ; v1(3725,3400) 3725,3380 3695,3350 3695,3230 4025,2900 4100,2900 CN9.5@4150,2850
PB0: CN1.9 CN11.51 U8.46 U17.3 | length 8010
  TopLayer w5: U17.3@1050,1275 1150,1275 1440,1565 1440,1990 1515,2065 1515,2440 1575,2500 1840,2500 v1(1915,2575) ; U8.46@2454.13,3857.68 2557.32,3857.68 2660,3755 2660,3565 2735,3490 3085,3490 3225,3350 CN11.51@3325,3350
  BottomLayer w5: v1(1915,2575) 1975,2575 2085,2685 2370,2685 2515,2830 2515,3390 2550,3425 2550,3450 2650,3550 v1(2675,3550) ; CN1.9@2825,6300 2885,6360 3140,6360 3165,6335 3165,5950 3150,5935 3150,4741.42 3215,4676.42 3215,3840 3265,3790 3265,3410 CN11.51@3325,3350
PB1: CN1.13 CN6.7 CN11.47 U8.47 | length 5977.4
  TopLayer w5: U8.47@2454.13,3877.36 2491.78,3877.36 2499.14,3870 2560,3870 2670,3760 2670,3579 2749,3500 3100,3500 3150,3550 CN11.47@3325,3550 3375,3500 3450,3500 3495,3545 3495,3870 3875,4250 4100,4250 CN6.7@4150,4300
  BottomLayer w5: CN1.13@2625,6300 2695,6370 3145,6370 3175,6340 3175,5940 3160,5925 3160,4745.56 3225,4680.56 3225,3850 3275,3800 3275,3600 CN11.47@3325,3550
PB2: CN11.45 R35.2 R43.1 U8.48 | length 1449.3
  TopLayer w5: U8.48@2454.13,3897.05 2486.24,3897.05 2503.28,3880 2565,3880 2687.5,3757.5 2687.5,3587.5 2765,3510 3085,3510 3225,3650 CN11.45@3325,3650 ; v1(2687.5,3377.5) R43.1@2725,3377.5 ; 2687.5,3700 R35.2@2722.5,3700
  BottomLayer w5: v1(2687.5,3377.5) 2687.5,3512.5 v1(2725,3550)
PB3: CN7.6 CN9.13 CN10.40 R50.2 R53.1 U8.133 | length 6178.8
  TopLayer w5: CN10.40@725,3950 785,3890 1545,3890 1552.05,3897.05 1732.95,3897.05 v1(1735,3895) ; v1(1875,2870) 2025.71,2870 2140.71,2755 2505,2755 2650,2610 2650,2410 2670,2390 3031.57,2390 3051.57,2370 3465,2370 3535,2440 3535,3145 3565,3175 3565,3330 3585,3350 v1(3725,3350) ; R53.1@3852.5,2925 3852.5,3052.5 4000,3200 4100,3200 CN9.13@4150,3250
  BottomLayer w5: v1(1735,3895) 1745,3885 1745,3605 1810,3540 1810,3044.14 1875,2979.14 v1(1875,2870) ; v1(3725,3350) 3750,3325 3975,3325 4000,3300 4100,3300 CN9.13@4150,3250
PB4: C51.2 CN9.3 CN10.41 JP19.1 JP20.2 R61.2 R64.1 U8.134 | length 5051.1
  TopLayer w5: CN10.41@625,3850 675,3900 750,3900 772.64,3877.36 1722.64,3877.36 v1(1725,3875) ; v1(1850,2915) 2035,2915 2070,2880 2410,2880 2700,2590 JP19.1@2700,2550 JP20.2@2850,2550 ; v1(2895,2330) 2901.84,2336.84 3013.16,2336.84 3030,2320 3490,2320 3665,2495 3695,2495 3702.5,2502.5 C51.2@3702.5,2525 R64.1@3797.5,2525 ; R64.1@3800,2527.5 3800,2550 3852.5,2602.5 3852.5,2652.5 3900,2700 4100,2700 CN9.3@4150,2750
  BottomLayer w5: v1(1725,3875) 1735,3865 1735,3595 1800,3530 1800,3040 1850,2990 v1(1850,2915) ; JP20.2@2850,2550 2895,2505 v1(2895,2330)
PB5: C5.2 CN1.29 CN6.10 CN10.42 JP11.1 U8.135 | length 9261.8
  TopLayer w5: CN10.42@725,3860 v1(850,3860) 857.36,3867.36 1432.64,3867.36 v1(1440,3860) U8.135@1593.54,3860 ; CN1.29@1825,6300 1875,6250 1875,6175 2050,6000 C5.2@2050,5852.5
  BottomLayer w5: v1(850,3860) 860,3870 860,4270 825,4305 825,5750 1200,6125 1725,6125 1775,6175 1775,6250 1915,6390 3235,6390 3750,5875 3750,4700 CN6.10@4050,4400 ; JP11.1@1425,2975 1425,3025 1440,3040 v1(1440,3860)
PB6: CN6.3 CN10.43 R44.2 U8.136 U10.9 | length 9168.5
  TopLayer w5: CN10.43@625,3750 675,3800 820,3800 877.36,3857.36 1402.64,3857.36 1422.01,3837.99 U8.136@1595.87,3837.99 ; R44.2@1352.5,3200 v1(1420,3200) ; v1(1725,1775) 1731.1,1768.9 U10.9@1830.51,1768.9 ; v1(2725,2825) 2750,2800 3450,2800 3475,2825 3475,3175 3505,3205 3505,3495 3525,3515 3525,3825 3750,4050 4100,4050 CN6.3@4150,4100
  BottomLayer w5: v1(1420,3840) 1420,3045 1385,3010 1385,2115 1745,1755 1745,1430 1900,1275 2725,1275 2925,1475 2925,2075 2825,2175 2825,2200 2615,2410 2615,2740 2700,2825 v1(2725,2825)
PB7: CN6.5 CN10.44 R38.2 U8.137 U10.10 | length 8902.2
  TopLayer w5: CN10.44@725,3750 785,3750 882.36,3847.36 1377.64,3847.36 1406.69,3818.31 U8.137@1595.87,3818.31 ; R38.2@1352.5,3275 v1(1400,3275) ; v1(1725.79,1749.21) U10.10@1830.51,1749.21 ; v1(2950,1850) v1(3575,1850)
  BottomLayer w5: v1(1400,3825) 1400,3050 1375,3025 1375,2100 v1(1725.79,1749.21) 1725.79,1424.21 1885,1265 2740,1265 2950,1475 v1(2950,1850) ; v1(3575,1850) 3595,1870 3595,4095 3750,4250 4100,4250 CN6.5@4150,4200
PB8: CN10.45 R32.2 U8.139 | length 2958.8
  TopLayer w5: CN10.45@625,3650 675,3700 750,3700 887.36,3837.36 1362.64,3837.36 1421.06,3778.94 1640.32,3778.94 1650,3788.62 2256.38,3788.62 2390,3655 2480.86,3655 2510.86,3625 2525,3625 v1(2550,3600) ; v1(2855,4025) 2950,4025 2977.5,3997.5 R32.2@3025,3997.5
  BottomLayer w5: v1(2550,3600) 2565,3615 2765,3615 2855,3705 v1(2855,4025)
PB9: CN10.46 U4.1 U8.140 | length 2805.5
  TopLayer w5: CN10.46@725,3650 725,3659.14 893.22,3827.36 1347.64,3827.36 1415.75,3759.25 1639.25,3759.25 1658.62,3778.62 2250.52,3778.62 2384.14,3645 2443,3645 v1(2450,3638) ; v1(2850,4050) 2875,4075 U4.1@2875,4175
  BottomLayer w5: v1(2450,3638) 2567,3638 2580,3625 2750,3625 2835,3710 2835,4035 v1(2850,4050)
PB10: CN11.24 R94.2 U8.69 | length 5728.2
  TopLayer w5: R94.2@1652.5,1250 1700,1250 v1(1850,1100) ; U8.69@2454.2,4310.5 2615.5,4310.5 2645,4340 3050,4340 3155,4445 3155,4580 3275,4700 3375,4700 CN11.24@3425,4750
  BottomLayer w5: v1(1850,1100) 2625,1100 3000,1475 3000,2050 2920,2130 2920,2525 2905,2540 2905,4060.86 2840,4125.86 v1(2840,4340)
PB11: CN11.23 U8.70 U17.20 | length 5433.3
  TopLayer w5: U17.20@1450,975 1400,975 1325,1050 1325,1400 1460,1535 1460,1960 v1(1585,2085) ; v1(2400,4325) 2405.12,4330.12 2514.88,4330.12 2524.5,4320.5 2600,4320.5 2638.44,4358.94 2846.56,4358.94 2855.5,4350 3040,4350 3140,4450 3140,4590 3300,4750 CN11.23@3325,4750
  BottomLayer w5: v1(1585,2085) 1860,2360 1860,2635 1950,2725 2350,2725 2475,2850 2475,3425 2335,3565 2335,3860 2410,3935 2410,4315 v1(2400,4325)
PB12: CN1.21 CN11.22 U8.73 U10.13 U17.24 | length 8627.4
  TopLayer w5: U17.24@1450,1175 1400,1175 1345,1230 1345,1370 1480,1505 1480,1705 1525,1750 1675,1750 1734.84,1690.16 U10.13@1830.51,1690.16 ; v1@1780,1690 v1(1780.16,1690.16) ; v1@2369.49,4380.51 2369.49,4694.49 2550,4875 2575,4875 2750,5050 3050,5050 3290,4810 3385,4810 CN11.22@3425,4850
  BottomLayer w5: v1(1780.16,1690.16) 1890.16,1690.16 1985,1785 1985,2115 1880,2220 1880,2626.72 1958.28,2705 2360,2705 2495,2840 2495,3435 2355,3575 2355,3850.86 2430,3925.86 2430,4345 2395,4380 v1(2370,4380) ; CN1.21@2225,6300 2305,6380 3155,6380 3185,6350 v1(3185,4915)
PB13: CN11.21 U8.74 U10.14 | length 5093.3
  TopLayer w5: v1(1800,1670) 1800.47,1670.47 U10.14@1830.51,1670.47 ; v1(2350,4400) 2350,4453.94 U8.74@2349.8,4454.13 2349.8,4691.66 2543.14,4885 2560,4885 2735,5060 3065,5060 3275,4850 CN11.21@3325,4850
  BottomLayer w5: v1(1800,1670) 1895,1670 1995,1770 1995,2130 1890,2235 1890,2622.57 1962.43,2695 2365,2695 2505,2835 2505,3439.14 2365,3579.14 2365,3845 2440,3920 2440,4360 2400,4400 v1(2350,4400)
PB14: CN11.20 JP14.3 U8.75 | length 4735.2
  TopLayer w5: v1(2330,4675) 2330,4686 2544,4900 2550,4900 2720,5070 3080,5070 3250,4900 3375,4900 CN11.20@3425,4950 ; U8.75@2330.12,4454.13 v1@2330.12,4675
  BottomLayer w5: JP14.3@1425,2650 1465,2690 1465,3010 1450,3025 1450,3835 1465,3850 1465,4765 1600,4900 1850,4900 1890,4860 2145,4860 v1(2330,4675)
PB15: CN11.18 U8.76 U10.11 | length 5147.1
  TopLayer w5: v1(1799.53,1729.53) U10.11@1830.51,1729.53 ; v1(2310,4400) 2310,4453.7 U8.76@2310.43,4454.13 2310.43,4685.43 2705,5080 3095,5080 3175,5000 3375,5000 CN11.18@3425,5050
  BottomLayer w5: v1(1799.53,1729.53) 1904.53,1729.53 1975,1800 1975,2100 1870,2205 1870,2630.86 1954.14,2715 2355,2715 2485,2845 2485,3430 2345,3570 2345,3855 2420,3930 2420,4335 2395,4360 2350,4360 v1(2310,4400)
PC0: C7.2 CN11.66 R6.2 R63.2 U8.26 | length 5620
  TopLayer w5: U8.26@2170,3593.23 2170,3145 2340,2975 R63.2@2362.5,2975 2362.5,2952.5 2365,2950 2475,2950 2735,2690 3160,2690 3250,2600 3375,2600 CN11.66@3425,2650 ; v1(2575,5750) R6.2@2575,5797.5 C7.2@2650,5797.5
  BottomLayer w5: v1(2575,5750) 2590,5735 2890,5735 3100,5525 3100,4720.71 3165,4655.71 3165,3110 3200,3075 v1(3200,2650)
PC1: C22.2 CN11.65 R5.1 U8.27 | length 5397.5
  TopLayer w5: U8.27@2192.32,3595.87 2192.32,3471.46 2180,3459.14 2180,3165 2295,3050 C22.2@2362.5,3050 2362.5,3022.5 2370,3015 2435,3015 2750,2700 v1(3180,2700) 3180,2695 3225,2650 CN11.65@3325,2650 ; v1(2500,5750) R5.1@2500,5797.5
  BottomLayer w5: v1(2500,5750) 2525,5725 2875,5725 3090,5510 3090,4716.57 3155,4651.57 3155,3095 3180,3070 v1(3180,2700)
